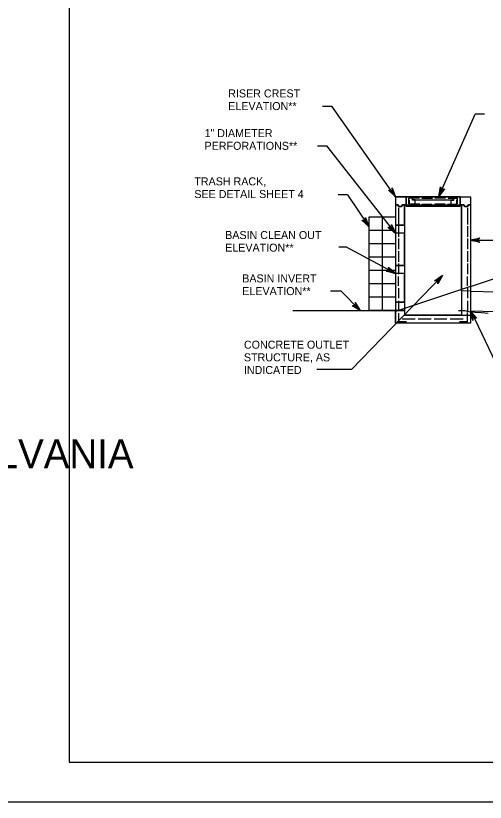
# Model space of a CAD drawing. Extents: x 636462 to 639890, y 299944 to 300538.
# Drawn here: x 638163.9 to 638339.9, y 299944.4 to 300239.1 of the extents above; entities that cross this region are included whole.
import ezdxf

# ---------------------------------------------------------------- set-up
doc = ezdxf.new("R2010")
doc.units = 0
for name, color, linetype in [('1', 7, 'Continuous'), ('Default', 7, 'Continuous'), ('PLT-BNDY', 7, 'Continuous')]:
    doc.layers.add(name, color=color, linetype=linetype)

msp = doc.modelspace()

# ---------------------------------------------------------------- linework, layer by layer
at = {"layer": '1'}
msp.add_lwpolyline([(638969.91, 299959.45), (638969.91, 300523.45), (638183.91, 300523.45), (638183.91, 299959.45), (638969.91, 299959.45), (638969.91, 299985.81), (638769.91, 299985.81), (638769.91, 300050.49), (638969.91, 300050.49), (638969.91, 300079.45), (638769.91, 300079.45), (638769.91, 299959.45), (638848.72, 299959.45), (638848.72, 299985.81), (638848.72, 299959.45), (638925.72, 299959.45), (638925.72, 299985.81), (638925.72, 299973.49), (638969.91, 299973.49)], dxfattribs=at)
at = {"layer": 'Default'}
for p, q in [((638278.87, 300205.25), (638282.37, 300205.25)), ((638306.25, 300171.25), (638282.37, 300205.25)), ((638322.47, 300171.42), (638336.1, 300202.21)), ((638339.6, 300202.21), (638336.1, 300202.21)), ((638277.03, 300190.32), (638280.54, 300190.32)), ((638306.25, 300157.59), (638280.54, 300190.32)), ((638288.23, 300171.96), (638284.73, 300171.96)), ((638288.23, 300171.96), (638296.25, 300160.11)), ((638306.25, 300171.25), (638306.25, 300123.92)), ((638306.25, 300171.25), (638334.33, 300171.25)), ((638310.18, 300167.75), (638310.18, 300171.25)), ((638330.4, 300171.25), (638310.18, 300171.25)), ((638312.71, 300170.16), (638312.71, 300171.25)), ((638327.87, 300170.16), (638327.87, 300171.25)), ((638330.4, 300167.75), (638330.4, 300171.25)), ((638334.33, 300171.25), (638334.33, 300123.92)), ((638306.25, 300168.2), (638307.05, 300168.2)), ((638307.05, 300168.2), (638307.43, 300167.68)), ((638308.43, 300167.68), (638308.82, 300168.2)), ((638308.82, 300168.2), (638309.62, 300168.2)), ((638309.62, 300168.2), (638330.96, 300168.2)), ((638309.62, 300168.2), (638309.62, 300127.9)), ((638315.17, 300170.7), (638311.18, 300170.7)), ((638311.18, 300168.62), (638311.18, 300170.7)), ((638311.51, 300168.44), (638311.51, 300170.1)), ((638315.31, 300168.44), (638311.51, 300168.44)), ((638312.54, 300170.02), (638312.54, 300171.08)), ((638313.35, 300170.02), (638312.54, 300170.02)), ((638312.71, 300170.16), (638313.55, 300170.16)), ((638313.55, 300167.75), (638313.55, 300170.16)), ((638313.55, 300170.16), (638327.03, 300170.16)), ((638316.05, 300168.44), (638319.84, 300168.44)), ((638316.11, 300170.7), (638320.1, 300170.7)), ((638324.97, 300170.7), (638320.98, 300170.7)), ((638324.78, 300168.44), (638320.99, 300168.44)), ((638325.69, 300168.44), (638329.18, 300168.44)), ((638325.91, 300170.7), (638329.52, 300170.7)), ((638327.03, 300167.75), (638327.03, 300170.16)), ((638327.03, 300170.16), (638327.87, 300170.16)), ((638327.23, 300170.02), (638328.04, 300170.02)), ((638328.04, 300170.02), (638328.04, 300171.08)), ((638329.18, 300168.44), (638329.18, 300170.1)), ((638329.52, 300168.62), (638329.52, 300170.7)), ((638330.96, 300168.2), (638330.96, 300126.97)), ((638330.96, 300168.2), (638331.76, 300168.2)), ((638331.76, 300168.2), (638332.15, 300167.68)), ((638333.15, 300167.68), (638333.53, 300168.2)), ((638333.53, 300168.2), (638334.33, 300168.2)), ((638307.35, 300167.07), (638307.35, 300160.89)), ((638307.43, 300167.68), (638308.43, 300167.68)), ((638310.18, 300167.75), (638330.4, 300167.75)), ((638332.15, 300167.68), (638333.15, 300167.68)), ((638333.18, 300167.07), (638333.18, 300160.89)), ((638296.25, 300163.59), (638296.25, 300128.61)), ((638306.25, 300163.59), (638296.25, 300163.59)), ((638301.25, 300163.59), (638301.25, 300128.61)), ((638309.62, 300160.62), (638306.25, 300160.62)), ((638307.35, 300160.24), (638307.35, 300156.24)), ((638333.18, 300160.24), (638333.18, 300156.24)), ((638306.25, 300158.59), (638296.25, 300158.59)), ((638309.62, 300157.59), (638306.25, 300157.59)), ((638306.25, 300153.6), (638296.25, 300153.6)), ((638307.35, 300155.6), (638307.35, 300151.6)), ((638333.18, 300155.6), (638333.18, 300151.6)), ((638334.33, 300155.02), (638396.89, 300155.02)), ((638285.01, 300152.57), (638287.65, 300152.57)), ((638306.25, 300142.5), (638287.65, 300152.57)), ((638307.35, 300150.95), (638307.35, 300146.95)), ((638333.18, 300150.95), (638333.18, 300146.95)), ((638306.25, 300148.6), (638296.25, 300148.6)), ((638309.62, 300145.53), (638306.25, 300145.53)), ((638307.35, 300146.3), (638307.35, 300142.3)), ((638333.18, 300146.3), (638333.18, 300142.3)), ((638323.9, 300141.74), (638289.77, 300106.52)), ((638306.25, 300143.6), (638296.25, 300143.6)), ((638309.62, 300142.5), (638306.25, 300142.5)), ((638307.35, 300137.91), (638307.35, 300141.39)), ((638333.18, 300137.91), (638333.18, 300141.39)), ((638281.88, 300136.09), (638285.78, 300136.09)), ((638293.04, 300128.61), (638285.78, 300136.09)), ((638306.25, 300138.61), (638296.25, 300138.61)), ((638334.33, 300137.61), (638306.25, 300128.25)), ((638307.35, 300136.98), (638307.35, 300133.27)), ((638334.33, 300135.96), (638330.96, 300136)), ((638333.18, 300136.98), (638333.18, 300133.27)), ((638334.33, 300135.96), (638343.91, 300135.62)), ((638306.25, 300133.61), (638296.25, 300133.61)), ((638309.62, 300131.82), (638306.25, 300131.82)), ((638307.35, 300132.32), (638307.35, 300128.49)), ((638333.18, 300132.32), (638333.18, 300128.54)), ((638267.79, 300128.61), (638306.25, 300128.61)), ((638306.25, 300128.61), (638296.25, 300128.61)), ((638309.62, 300128.7), (638306.25, 300128.7)), ((638307.35, 300127.72), (638307.35, 300124.41)), ((638309.62, 300127.9), (638309.62, 300126.97)), ((638330.96, 300126.97), (638309.62, 300126.97)), ((638330.96, 300126.97), (638334.33, 300126.92)), ((638333.18, 300124.41), (638333.18, 300127.94)), ((638343.65, 300128.13), (638334.33, 300128.46)), ((638334.56, 300128.26), (638346.48, 300103.5)), ((638310.38, 300124.41), (638307.35, 300124.41)), ((638308.76, 300125.56), (638313.61, 300125.56)), ((638314.73, 300125.56), (638319.59, 300125.56)), ((638320.7, 300125.56), (638325.46, 300125.56)), ((638326.67, 300125.56), (638331.53, 300125.56)), ((638333.18, 300124.41), (638330.15, 300124.41)), ((638334.33, 300123.92), (638306.25, 300123.92)), ((638289.77, 300106.52), (638276.8, 300106.52))]:
    msp.add_line(p, q, dxfattribs=at)
for points in [[(638305, 300174.3), (638305.04, 300174.65), (638306.25, 300171.25), (638305, 300174.3), (638304.8, 300173.93), (638306.25, 300171.25), (638304.36, 300173.64), (638303.95, 300173.58), (638306.25, 300171.25), (638303.58, 300173.68), (638303.95, 300173.58)], [(638324.34, 300174.13), (638324.65, 300174.29), (638322.47, 300171.42), (638324.34, 300174.13), (638323.92, 300174.1), (638322.47, 300171.42), (638323.44, 300174.3), (638323.16, 300174.62), (638322.47, 300171.42), (638323.04, 300174.98), (638323.16, 300174.62)], [(638334.33, 300137.61), (638423.52, 300167.34), (638444.76, 300167.34), (638465.99, 300167.34)], [(638294.97, 300163.15), (638295.01, 300163.5), (638296.25, 300160.11), (638294.97, 300163.15), (638294.77, 300162.78), (638296.25, 300160.11), (638294.34, 300162.48), (638293.93, 300162.42), (638296.25, 300160.11), (638293.56, 300162.51), (638293.93, 300162.42)], [(638304.75, 300160.52), (638304.76, 300160.87), (638306.25, 300157.59), (638304.75, 300160.52), (638304.58, 300160.14), (638306.25, 300157.59), (638304.17, 300159.81), (638303.76, 300159.72), (638306.25, 300157.59), (638303.39, 300159.79), (638303.76, 300159.72)], [(638337.57, 300154.38), (638337.84, 300154.16), (638334.33, 300155.02), (638337.57, 300154.38), (638337.37, 300154.76), (638334.33, 300155.02), (638337.36, 300155.28), (638337.55, 300155.65), (638334.33, 300155.02), (638337.83, 300155.91), (638337.55, 300155.65)], [(638303.69, 300144.58), (638303.56, 300144.9), (638306.25, 300142.5), (638303.69, 300144.58), (638303.69, 300144.16), (638306.25, 300142.5), (638303.45, 300143.69), (638303.11, 300143.45), (638306.25, 300142.5), (638302.75, 300143.35), (638303.11, 300143.45)], [(638321.2, 300139.85), (638320.85, 300139.81), (638323.9, 300141.74), (638321.2, 300139.85), (638321.6, 300139.73), (638323.9, 300141.74), (638321.98, 300139.37), (638322.13, 300138.98), (638323.9, 300141.74), (638322.11, 300138.6), (638322.13, 300138.98)], [(638291.2, 300131.35), (638291.17, 300131.7), (638293.04, 300128.61), (638291.2, 300131.35), (638291.08, 300130.94), (638293.04, 300128.61), (638290.71, 300130.57), (638290.32, 300130.43), (638293.04, 300128.61), (638289.94, 300130.45), (638290.32, 300130.43)], [(638329.83, 300128.61), (638332.15, 300128.61), (638333.55, 300128.29), (638335.98, 300128.08), (638338.41, 300127.86), (638340.96, 300127.64)], [(638335.25, 300125.29), (638335.18, 300124.95), (638334.33, 300128.46), (638335.25, 300125.29), (638335.5, 300125.64), (638334.33, 300128.46), (638335.96, 300125.89), (638336.37, 300125.9), (638334.33, 300128.46), (638336.73, 300125.76), (638336.37, 300125.9)]]:
    msp.add_lwpolyline(points, dxfattribs=at)
for points in [[(638306.25, 300171.25), (638306.25, 300168.2), (638307.05, 300168.2), (638307.43, 300167.68), (638308.43, 300167.68), (638308.82, 300168.2), (638310.18, 300168.2), (638310.18, 300171.25)], [(638312.71, 300171.25), (638310.18, 300171.25), (638310.18, 300167.75), (638313.55, 300167.75), (638313.55, 300170.16), (638312.71, 300170.16)], [(638330.4, 300171.25), (638330.4, 300167.75), (638327.03, 300167.75), (638327.03, 300170.16), (638327.87, 300170.16), (638327.87, 300171.25)], [(638330.4, 300171.25), (638334.33, 300171.25), (638334.33, 300168.2), (638333.53, 300168.2), (638333.15, 300167.68), (638332.15, 300167.68), (638331.76, 300168.2), (638330.4, 300168.2)], [(638309.62, 300160.64), (638309.62, 300168.2), (638308.82, 300168.2), (638308.43, 300167.68), (638307.43, 300167.68), (638307.05, 300168.2), (638306.25, 300168.2), (638306.25, 300160.64)], [(638330.96, 300168.2), (638331.76, 300168.2), (638332.15, 300167.68), (638333.15, 300167.68), (638333.53, 300168.2), (638334.33, 300168.2), (638334.31, 300135.96), (638330.94, 300136.01)], [(638309.62, 300145.53), (638309.62, 300157.61), (638306.25, 300157.61), (638306.25, 300145.53)], [(638309.62, 300131.82), (638309.62, 300142.47), (638306.25, 300142.47), (638306.25, 300131.82)], [(638334.33, 300126.92), (638334.33, 300123.92), (638306.25, 300123.92), (638306.25, 300128.69), (638309.62, 300128.69), (638309.62, 300126.97), (638330.96, 300126.97)]]:
    msp.add_lwpolyline(points, close=True, dxfattribs=at)
at = {"layer": 'PLT-BNDY'}
msp.add_lwpolyline([(638143.91, 300538.45), (638984.91, 300538.45), (638984.91, 299944.45), (638143.91, 299944.45)], close=True, dxfattribs=at)

# ---------------------------------------------------------------- texts
at = {"layer": '1'}
msp.add_text('COMMONWEALTH OF PENNSYLVANIA', height=10.7834, dxfattribs=at).set_placement((637942.07, 300069.59))
at = {"layer": 'Default'}
for s, p in [('RISER CREST', (638243.55, 300208.48)), ('ELEVATION**', (638243.55, 300203.74)), ('1" DIAMETER', (638234.67, 300193.6)), ('PERFORATIONS**', (638234.67, 300188.85)), ('TRASH RACK,', (638230.84, 300175.53)), ('SEE DETAIL SHEET 4', (638230.84, 300170.78)), ('BASIN CLEAN OUT', (638242.4, 300155.44)), ('ELEVATION**', (638242.4, 300150.7)), ('BASIN INVERT', (638248.8, 300139.18)), ('ELEVATION**', (638248.8, 300134.43)), ('CONCRETE OUTLET', (638249.43, 300114.36)), ('STRUCTURE, AS', (638249.43, 300109.61)), ('INDICATED', (638249.43, 300104.87))]:
    msp.add_text(s, height=2.998, dxfattribs=at).set_placement(p)

doc.saveas('drawing.dxf')
